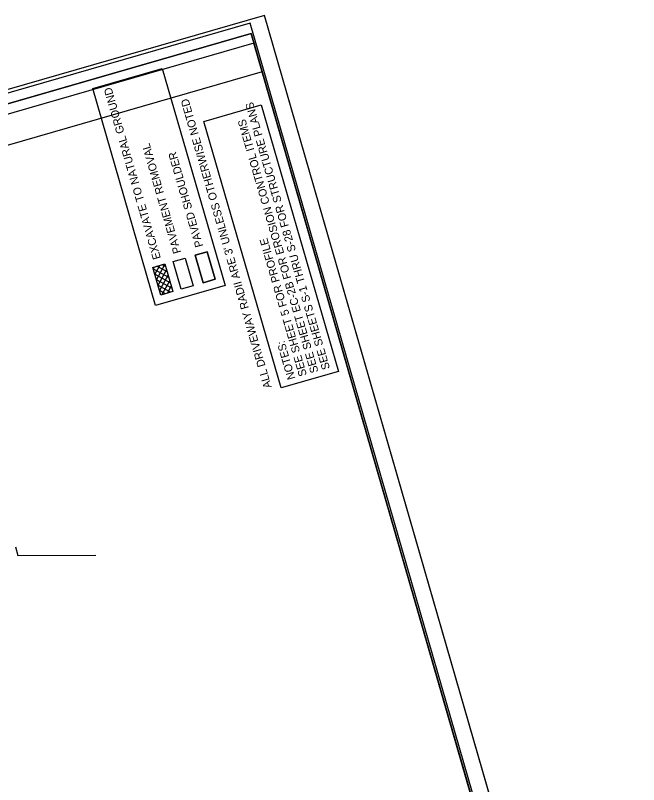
# Model space of a CAD drawing. Extents: x 2167139 to 2168658, y 842502 to 844423.
# Drawn here: x 2167880 to 2168658, y 843463 to 844423 of the extents above; entities that cross this region are included whole.
import ezdxf

# ---------------------------------------------------------------- set-up
doc = ezdxf.new("R2010")
doc.units = 0
for name, color, linetype in [('Default', 7, 'Continuous'), ('Old_Level_1', 7, 'Continuous'), ('Old_Level_2', 7, 'Continuous'), ('Prop Dimension', 7, 'Continuous'), ('Prop Shade Light', 7, 'Continuous'), ('Sheet Clip Boundary CELL', 7, 'Continuous'), ('Sheet Cutting Line CELL', 7, 'Continuous'), ('Sheet Layout Plan Border', 7, 'Continuous'), ('Sheet Plan CELL', 7, 'Continuous'), ('Sheet Plan Layout CELL', 7, 'Continuous'), ('Sheet Plot Border Inside CELL', 7, 'Continuous'), ('Sheet Plot Border Outside CELL', 7, 'Continuous')]:
    doc.layers.add(name, color=color, linetype=linetype)

msp = doc.modelspace()

# ---------------------------------------------------------------- linework, layer by layer
at = {"layer": 'Default'}
for p, q in [((2168071.3, 844095.95), (2168052.03, 844106.58)), ((2168052.05, 844106.5), (2168053.44, 844109.03)), ((2168054.01, 844099.71), (2168060.24, 844111)), ((2168055.97, 844092.92), (2168066.61, 844112.19)), ((2168069.34, 844102.74), (2168056.39, 844109.88)), ((2168067.37, 844109.53), (2168063.18, 844111.85)), ((2168073.26, 844089.15), (2168053.99, 844099.79)), ((2168057.93, 844086.12), (2168068.57, 844105.39)), ((2168059.89, 844079.33), (2168070.53, 844098.6)), ((2168075.22, 844082.36), (2168055.95, 844093)), ((2168062.87, 844074.38), (2168072.49, 844091.81)), ((2168073.67, 844077.5), (2168057.91, 844086.2)), ((2168066.88, 844075.54), (2168059.87, 844079.41)), ((2168069.67, 844076.34), (2168074.45, 844085.01))]:
    msp.add_line(p, q, dxfattribs=at)
at = {"layer": 'Old_Level_1'}
for p, q in [((2168051.48, 844108.47), (2168066.44, 844112.78)), ((2168061.44, 844073.97), (2168051.48, 844108.47)), ((2168066.44, 844112.78), (2168076.4, 844078.29)), ((2168076.4, 844078.29), (2168061.44, 844073.97))]:
    msp.add_line(p, q, dxfattribs=at)
at = {"layer": 'Old_Level_2'}
for p, q in [((2168104.38, 844123.74), (2168119.33, 844128.06)), ((2168119.33, 844128.06), (2168129.29, 844093.56)), ((2168076.77, 844115.77), (2168091.72, 844120.09)), ((2168091.72, 844120.09), (2168101.68, 844085.59)), ((2168114.34, 844089.24), (2168104.38, 844123.74)), ((2168086.73, 844081.27), (2168076.77, 844115.77)), ((2168129.29, 844093.56), (2168114.34, 844089.24)), ((2168101.68, 844085.59), (2168086.73, 844081.27))]:
    msp.add_line(p, q, dxfattribs=at)
for points in [[(2168054.8, 844060.88), (2167976.51, 844331.82), (2168063.28, 844356.9), (2168141.58, 844085.96)], [(2168211.51, 843957.91), (2168115.31, 844290.7), (2168186.88, 844311.38), (2168283.08, 843978.59)]]:
    msp.add_lwpolyline(points, close=True, dxfattribs=at)
at = {"layer": 'Prop Dimension'}
for p, q in [((2167879.91, 843759.33), (2167882.93, 843748.86)), ((2167882.93, 843748.86), (2167980.13, 843749.24))]:
    msp.add_line(p, q, dxfattribs=at)
at = {"layer": 'Prop Shade Light'}
for p, q in [((2168119.33, 844128.06), (2168104.38, 844123.74)), ((2168129.29, 844093.56), (2168119.33, 844128.06)), ((2168104.38, 844123.74), (2168114.34, 844089.24)), ((2168114.34, 844089.24), (2168129.29, 844093.56))]:
    msp.add_line(p, q, dxfattribs=at)
at = {"layer": 'Sheet Clip Boundary CELL'}
msp.add_lwpolyline([(2168333.42, 842899.61), (2168359.34, 842906.72), (2168266.95, 843188.11), (2168382.06, 843220.66), (2168502.28, 843263.66), (2168187.91, 844352.53), (2167382.3, 844119.94), (2167434.8, 843938.11), (2167231.61, 843879.44), (2167577.57, 842681.16)], close=True, dxfattribs=at)
at = {"layer": 'Sheet Cutting Line CELL'}
msp.add_line((2168657.93, 842805.71), (2168190.95, 844423.15), dxfattribs=at)
at = {"layer": 'Sheet Layout Plan Border'}
msp.add_lwpolyline([(2168586.35, 842975.21), (2168177.55, 844388.42), (2167371.94, 844155.82), (2167434.8, 843938.11), (2167231.61, 843879.44), (2167577.55, 842683.96)], close=True, dxfattribs=at)
at = {"layer": 'Sheet Plan CELL'}
for points in [[(2167165.23, 844109.34), (2167581.32, 842668.17), (2168590.12, 842959.42), (2168174.04, 844400.57)], [(2168590.12, 842959.42), (2167581.35, 842668.15), (2167220.72, 843917.11), (2167364.89, 843958.75), (2167309.41, 844150.94), (2168174.04, 844400.57)]]:
    msp.add_lwpolyline(points, close=True, dxfattribs=at)
at = {"layer": 'Sheet Plan Layout CELL'}
msp.add_lwpolyline([(2167581.35, 842668.15), (2168590.12, 842959.42), (2168174.04, 844400.56), (2167368.43, 844167.97), (2167434.8, 843938.11), (2167231.61, 843879.44)], close=True, dxfattribs=at)
at = {"layer": 'Sheet Plot Border Inside CELL'}
msp.add_lwpolyline([(2168635.11, 842812.65), (2168172.98, 844413.26), (2167159.38, 844120.64), (2167621.51, 842520.01)], close=True, dxfattribs=at)
at = {"layer": 'Sheet Plot Border Outside CELL'}
msp.add_lwpolyline([(2168657.93, 842805.71), (2168190.95, 844423.15), (2167138.92, 844119.41), (2167605.9, 842501.98)], close=True, dxfattribs=at)

# ---------------------------------------------------------------- texts
at = {"layer": 'Old_Level_2'}
for s, rotation, p in [('EXCAVATE TO NATURAL GROUND', 106.12627, (2168061.57, 844119.96)), ("ALL DRIVEWAY RADII ARE 3' UNLESS OTHERWISE NOTED", 106.1042, (2168199.86, 843959.17)), ('SEE SHEETS S-1 THRU S-28 FOR STRUCTURE PLANS', 106.12627, (2168272.73, 843982.32)), ('SEE SHEET EC-2B FOR EROSION CONTROL ITEMS', 106.12627, (2168258.32, 843978.16)), ('PAVEMENT REMOVAL', 106.12627, (2168086.89, 844127.22)), ('PAVED SHOULDER', 106.12627, (2168114.45, 844135.15)), ('SEE SHEET 5 FOR PROFILE', 106.12627, (2168243.91, 843973.99)), ('NOTES:', 106.12627, (2168229.5, 843969.82))]:
    msp.add_text(s, height=10, rotation=rotation, dxfattribs=at).set_placement(p)

doc.saveas('drawing.dxf')
